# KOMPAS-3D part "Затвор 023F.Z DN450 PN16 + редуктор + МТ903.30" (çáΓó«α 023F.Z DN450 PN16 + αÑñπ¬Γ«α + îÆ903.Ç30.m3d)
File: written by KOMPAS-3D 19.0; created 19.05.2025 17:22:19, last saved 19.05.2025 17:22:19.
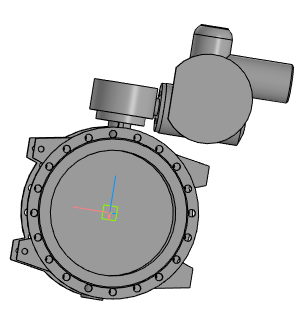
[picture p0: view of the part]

Document properties: Полное имя файла: Затвор 023F.Z DN450 PN16 + редуктор + МТ903.30.a3d

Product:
- Part/product: Затвор 023F.Z DN450 PN16 + редуктор + МТ903.30
    Масса: 390.303

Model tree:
1. Операция без истории:1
